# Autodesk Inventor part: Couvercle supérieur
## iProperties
Author: Philippe
Shininess: 20.0
Angle Display Precision: 2
Document Length Units: 11269
Document Angle Units: 11283
Document Time Units: 11279
Document Mass Units: 11290
Document Length Units Precision: 3
Document Angle Units Precision: 2
Compacted: False
PropertySet Name: _Private Model Information
Created: 2002-01
Part Number: Couvercle supérieur
Material: Par défaut
Document SubType Name: Modélisation
Designer: Philippe
Control State: 0
Master: False
Checked Out: False
PropertySet Name: Design Tracking Control
Density: 0.0
Volumn: 0.0
Area: 0.0
PropertySet Name: Model Information
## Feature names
1. Extrusion1
2. Extrusion2
3. Congé1 [Fillet]
4. Congé2 [Fillet]
5. Chanfrein1 [Chamfer]
6. Extrusion3
7. Congé3 [Fillet]
8. Coque1
9. Extrusion4
10. Extrusion5
11. Perçage1 [Hole]
12. Perçage2 [Hole]
13. Extrusion6
14. Extrusion7
15. Extrusion8
16. Extrusion10
17. Congé4 [Fillet]
